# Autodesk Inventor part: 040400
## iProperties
Shininess: 69.0
Length Units: 11269
Angle Units: 11279
Time Units: 11290
Mass Units: 11284
Length Display Precision: 3
Angle Display Precision: 2
Compacted: True
Company: Pneumax S.p.A.
Part Number: 040400
Material: Default
Description: GOMITO INNESTABILE Ø4
Document SubType Name: Modellazione
Catalog Web Link: www.pneumaxspa.com
Density: 1.59
Volumn: 0.8648857994912436
Area: 17.092995283760587
PropertySet Name: Model Information
Control State: 0
Master: False
Checked Out: False
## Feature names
1. Revolution6
2. Serie circolare3 [Circular Pattern]
3. Circular Pattern7
4. Rivoluzione5 [Revolution]
5. Foro6 [Hole]
6. Serie circolare6 [Circular Pattern]
